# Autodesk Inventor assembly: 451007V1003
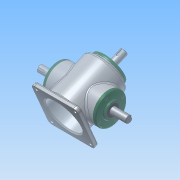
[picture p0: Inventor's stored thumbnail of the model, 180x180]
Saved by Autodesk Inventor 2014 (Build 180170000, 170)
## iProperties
Created: 2015-10
Part Number: 451007V1003
Document SubType Name: Assembly
Designer: net
Author: net
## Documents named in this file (14)
- C:\Users\net\Desktop\451007V1003\새 폴더\451007V1003.iam
- C:\Users\net\Desktop\451007V1003.ipt
- C:\Users\net\Desktop\451007V1003\서브 베벨기어.ipt
- C:\Users\net\Desktop\451007V1003\서브 축.ipt
- 서브 축.ipt
- C:\Users\net\Desktop\451007V1003\키 4x4.ipt
- C:\Users\net\Desktop\451007V1003\메인 베벨기어.ipt
- C:\Users\net\Desktop\451007V1003\메인 축.ipt
- 메인 축.ipt
- C:\Users\net\Desktop\451007V1003\키 5x5.ipt
- C:\Users\net\Desktop\451007V1003\베어링 6203.ipt
- C:\Users\net\Desktop\451007V1003\오일실.ipt
- C:\Users\net\Desktop\451007V1003\커버.ipt
- C:\Users\net\Desktop\451007V1003\M4.ipt
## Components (13 placed, 2 different names)
1. 451007V1003:1
2. M4:2
3. M4:4
4. M4:5
5. M4:6
6. M4:3
7. M4:7
8. M4:8
9. M4:9
10. M4:1
11. M4:10
12. M4:11
13. M4:12
## Named parameters: d33_d22 = 0, d34_d31 = 0, d35_d32 = 0, d36_d2 = 0, d37_d3 = 0, d38_d4 = 0, d39_d5 = 0, d40_d6 = 0, d41_d19 = 0, d42_d20 = 0, d43_d21 = 0, d44_d0 = 0, d75_d72 = 0, d77_d59_d51 = 0
